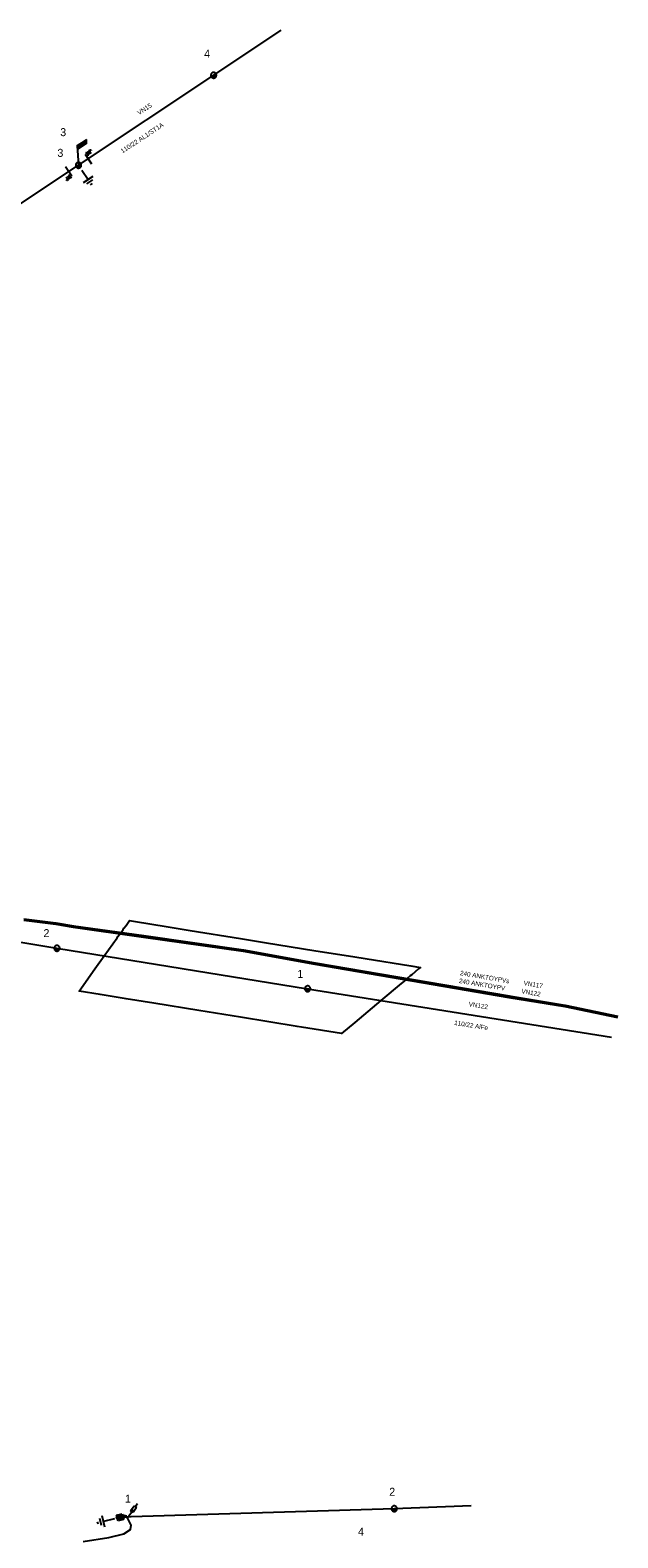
# Model space of a CAD drawing. Extents: x -540879 to -537255, y -1184046 to -1180016.
# Drawn here: x -537383.5 to -537255, y -1180686.9 to -1180357.2 of the extents above; entities that cross this region are included whole.
import ezdxf

# ---------------------------------------------------------------- set-up
doc = ezdxf.new("R2010")
doc.units = 0
for name, color, linetype in [('Default', 7, 'Continuous'), ('Vrstva 1', 7, 'Continuous'), ('Vrstva 11', 7, 'Continuous'), ('Vrstva 12', 7, 'Continuous'), ('Vrstva 13', 7, 'Continuous'), ('Vrstva 14', 7, 'Continuous'), ('Vrstva 15', 7, 'Continuous'), ('Vrstva 16', 7, 'Continuous'), ('Vrstva 18', 7, 'Continuous'), ('Vrstva 19', 7, 'Continuous'), ('Vrstva 2', 7, 'Continuous'), ('Vrstva 3', 7, 'Continuous'), ('Vrstva 35', 7, 'Continuous'), ('Vrstva 4', 7, 'Continuous'), ('Vrstva 5', 7, 'Continuous'), ('Vrstva 6', 7, 'Continuous'), ('Vrstva 7', 7, 'Continuous')]:
    doc.layers.add(name, color=color, linetype=linetype)

# ---------------------------------------------------------------- blocks, each defined once
blk = doc.blocks.new('VN840')
at = {"layer": 'Vrstva 15'}
for points in [[(-0.01, 1.41), (-0.01, -1.09)], [(-1.51, -1.24), (-1.51, -1.15)], [(-1.48, -1.35), (-1.51, -1.24)], [(-1.33, -1.42), (-1.48, -1.35)], [(-1.27, -1.42), (-1.33, -1.42)], [(-1.13, -1.35), (-1.27, -1.42)], [(-1.09, -1.24), (-1.13, -1.35)], [(-1.09, -0.59), (-1.09, -1.24)], [(-0.68, -0.59), (-0.68, -1.42)], [(-0.68, -1.11), (-0.27, -0.59)], [(-0.54, -0.94), (-0.2, -1.42)]]:
    blk.add_lwpolyline(points, dxfattribs=at)
blk = doc.blocks.new('VN440')
at = {"layer": 'Vrstva 2'}
for points in [[(1.22, 0), (1.21, 0.13), (1.19, 0.25), (1.16, 0.38), (1.11, 0.5), (1.05, 0.61), (0.98, 0.72), (0.9, 0.82), (0.81, 0.91), (0.71, 0.99), (0.6, 1.06), (0.49, 1.12), (0.37, 1.16), (0.25, 1.2), (0.12, 1.22), (-0.01, 1.22), (-0.14, 1.22), (-0.26, 1.2), (-0.39, 1.16), (-0.51, 1.12), (-0.62, 1.06), (-0.73, 0.99), (-0.83, 0.91), (-0.92, 0.82), (-1, 0.72), (-1.07, 0.61), (-1.13, 0.5), (-1.18, 0.38), (-1.21, 0.25), (-1.23, 0.13), (-1.24, 0), (-1.23, -0.13), (-1.21, -0.26), (-1.18, -0.38), (-1.13, -0.5), (-1.07, -0.62), (-1, -0.73), (-0.92, -0.83), (-0.83, -0.92), (-0.73, -1), (-0.62, -1.07), (-0.51, -1.13), (-0.39, -1.17), (-0.26, -1.2), (-0.14, -1.23), (-0.01, -1.23), (0.12, -1.23), (0.25, -1.2), (0.37, -1.17), (0.49, -1.13), (0.6, -1.07), (0.71, -1), (0.81, -0.92), (0.9, -0.83), (0.98, -0.73), (1.05, -0.62), (1.11, -0.5), (1.16, -0.38), (1.19, -0.26), (1.21, -0.13), (1.22, 0)], [(-1.24, 0), (1.22, 0)], [(-1.18, -0.34), (1.1, -0.34)], [(-1.01, -0.63), (0.97, -0.63)], [(-0.74, -0.92), (0.68, -0.92)]]:
    blk.add_lwpolyline(points, dxfattribs=at)
blk = doc.blocks.new('VN890')
at = {"layer": 'Vrstva 4'}
for points in [[(-0.41, 0.41), (0.41, 0)], [(-0.41, -0.41), (-0.41, 0.41)], [(0.41, 0), (-0.41, -0.41)], [(-0.34, 0.31), (0.27, 0), (-0.34, -0.3), (-0.34, 0.31)], [(-0.26, 0.2), (0.1, 0), (-0.26, -0.18), (-0.26, 0.2)], [(-0.19, 0.09), (-0.04, 0), (-0.19, -0.08), (-0.19, 0.09)], [(-0.16, -0.01), (-0.16, 0.03), (-0.13, 0.01), (-0.16, -0.01)]]:
    blk.add_lwpolyline(points, dxfattribs=at)
blk = doc.blocks.new('VN820')
at = {"layer": 'Vrstva 13'}
for points in [[(0, 0), (0, -2.1)], [(-0.32, -1.63), (0.34, -1.63)], [(-0.32, -2.95), (-0.32, -1.63)], [(0.34, -2.95), (-0.32, -2.95)], [(0, -2.1), (-0.12, -1.86)], [(0, -2.1), (0.12, -1.86)], [(0, -2.95), (0, -3.75)], [(0.34, -1.63), (0.34, -2.95)]]:
    blk.add_lwpolyline(points, dxfattribs=at)
blk = doc.blocks.new('VN810')
at = {"layer": 'Vrstva 14'}
for points in [[(0, -1.25), (0, -3.75)], [(1.25, -3.75), (-1.25, -3.75)], [(0.77, -4.37), (-0.8, -4.37)], [(0, -5), (-0.25, -5)], [(0.27, -5), (0, -5)]]:
    blk.add_lwpolyline(points, dxfattribs=at)
blk = doc.blocks.new('VN001')
at = {"layer": 'Default'}
for p, q in [((1.9, 3.33), (4.32, 3.33)), ((1.93, 3.38), (4.35, 3.38)), ((1.96, 3.43), (4.37, 3.43)), ((1.99, 3.48), (4.4, 3.48)), ((2.02, 3.53), (4.43, 3.53)), ((2.05, 3.58), (4.46, 3.58)), ((2.07, 3.63), (4.49, 3.63)), ((2.1, 3.68), (4.52, 3.68)), ((2.13, 3.73), (2.54, 3.73)), ((1.73, 3.03), (4.14, 3.03)), ((1.76, 3.08), (4.17, 3.08)), ((1.79, 3.13), (4.2, 3.13)), ((1.82, 3.18), (4.23, 3.18)), ((1.85, 3.23), (4.26, 3.23)), ((1.87, 3.28), (4.29, 3.28))]:
    blk.add_line(p, q, dxfattribs=at)
blk.add_lwpolyline([(2.13, 3.73), (0, 0)], dxfattribs=at)
blk.add_lwpolyline([(4.55, 3.73), (2.13, 3.73), (1.7, 2.98), (4.12, 2.99)], close=True, dxfattribs=at)
blk = doc.blocks.new('VN470')
at = {"layer": 'Vrstva 2'}
for points in [[(-1.23, 1.22), (1.23, 1.22)], [(-1.23, -1.23), (-1.23, 1.22)], [(-0.92, 0.9), (0.92, 0.9)], [(-0.92, -0.95), (-0.92, 0.9)], [(-0.61, 0.61), (0.61, 0.61)], [(-0.61, -0.62), (-0.61, 0.61)], [(-0.31, -0.27), (-0.31, 0.34)], [(-0.31, 0.34), (0.31, 0.34)], [(0, 1.22), (0, 1.97)], [(0.31, 0.34), (0.31, -0.27)], [(0.61, 0.61), (0.61, -0.62)], [(0.92, 0.9), (0.92, -0.95)], [(1.23, 1.22), (1.23, -1.23)], [(1.23, -1.23), (-1.23, -1.23)], [(0.92, -0.95), (-0.92, -0.95)], [(0.61, -0.62), (-0.61, -0.62)], [(0.31, -0.27), (-0.31, -0.27)], [(0, -1.23), (0, -1.98)]]:
    blk.add_lwpolyline(points, dxfattribs=at)

msp = doc.modelspace()

# ---------------------------------------------------------------- linework, layer by layer
at = {"layer": 'Vrstva 1'}
for points in [[(-537372.88, -1180386.77), (-537343.33, -1180367.08), (-537328.56, -1180357.22)], [(-537402.58, -1180406.43), (-537372.88, -1180386.77)], [(-537402.28, -1180553.89), (-537377.59, -1180557.99), (-537322.79, -1180566.84), (-537256.34, -1180577.46)], [(-537287.02, -1180679.9), (-537303.84, -1180680.55), (-537363.8, -1180682.43)]]:
    msp.add_lwpolyline(points, dxfattribs=at)
at = {"layer": 'Vrstva 35'}
msp.add_lwpolyline([(-537360.89, -1180552.08), (-537353.3, -1180553.3), (-537348.46, -1180554.08), (-537337.5, -1180555.86), (-537331.78, -1180556.78), (-537321.44, -1180558.45), (-537312.5, -1180559.88), (-537310.24, -1180560.24), (-537300.26, -1180561.83), (-537298.13, -1180562.17), (-537298.52, -1180562.5), (-537300.04, -1180563.78), (-537300.35, -1180564.03), (-537301.05, -1180564.62), (-537301.35, -1180564.87), (-537302.05, -1180565.46), (-537302.36, -1180565.72), (-537306.75, -1180569.4), (-537312.5, -1180574.22), (-537315.38, -1180576.63), (-537324.14, -1180575.23), (-537325.08, -1180575.08), (-537337.5, -1180573.07), (-537346.6, -1180571.6), (-537356.39, -1180570.02), (-537362.5, -1180569.04), (-537368.13, -1180568.13), (-537372.76, -1180567.38), (-537369.28, -1180562.5), (-537367.25, -1180559.66), (-537364.44, -1180555.72), (-537364.25, -1180555.45), (-537363.79, -1180554.8), (-537363.59, -1180554.53), (-537363.13, -1180553.89), (-537362.94, -1180553.61), (-537362.5, -1180552.99), (-537361.74, -1180551.94)], close=True, dxfattribs=at)
at = {"layer": 'Vrstva 5'}
for points in [[(-537384.86, -1180551.85), (-537377.85, -1180552.73), (-537374.02, -1180553.35), (-537358.66, -1180555.53), (-537336.87, -1180558.61), (-537321.18, -1180561.49), (-537278.79, -1180568.73), (-537266.53, -1180570.72), (-537255.05, -1180573.15)], [(-537384.82, -1180551.55), (-537377.81, -1180552.43), (-537373.97, -1180553.06), (-537358.61, -1180555.23), (-537336.82, -1180558.32), (-537321.12, -1180561.19), (-537278.74, -1180568.43), (-537266.47, -1180570.43), (-537254.97, -1180572.86)], [(-537371.83, -1180687.72), (-537366.25, -1180686.86), (-537363.01, -1180686.02), (-537361.48, -1180685.1), (-537361.36, -1180684.18), (-537362.15, -1180682.51), (-537363.12, -1180682.26), (-537363.8, -1180682.43)]]:
    msp.add_lwpolyline(points, dxfattribs=at)

# ---------------------------------------------------------------- block references
at = {"layer": 'Vrstva 11', "rotation": 33.72583887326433}
msp.add_blockref('VN001', (-537372.88, -1180386.77), dxfattribs=at)
at = {"layer": 'Vrstva 13'}
for name, p, xscale, yscale, rotation in [('VN440', (-537343.33, -1180367.08), 0.5, 0.5, 33.71625696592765), ('VN440', (-537372.88, -1180386.77), 0.5, 0.49999999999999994, 33.681768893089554), ('VN440', (-537377.59, -1180557.99), 0.49999999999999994, 0.5, -9.494450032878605), ('VN440', (-537322.79, -1180566.84), 0.5, 0.5000000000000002, -9.05749734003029), ('VN440', (-537303.84, -1180680.55), 0.5, 0.5, 1.7932083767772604), ('VN470', (-537363.8, -1180682.43), 0.5, 0.5000000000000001, 104.27390276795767)]:
    msp.add_blockref(name, p, dxfattribs=dict(at, xscale=xscale, yscale=yscale, rotation=rotation))
at = {"layer": 'Vrstva 15'}
for p, rotation in [((-537372.88, -1180386.77), 33.726074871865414), ((-537363.8, -1180682.43), -75.9637555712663)]:
    msp.add_blockref('VN810', p, dxfattribs=dict(at, rotation=rotation))
at = {"layer": 'Vrstva 16', "rotation": 145.1834055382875}
msp.add_blockref('VN820', (-537362.15, -1180682.51), dxfattribs=at)
at = {"layer": 'Vrstva 18'}
for p, rotation in [((-537370.73, -1180385.34), -146.60114536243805), ((-537374.97, -1180388.17), 33.725644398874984)]:
    msp.add_blockref('VN840', p, dxfattribs=dict(at, rotation=rotation))
at = {"layer": 'Vrstva 19', "rotation": 14.258491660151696}
msp.add_blockref('VN890', (-537362.77, -1180682.21), dxfattribs=at)

# ---------------------------------------------------------------- texts
at = {"layer": 'Vrstva 12'}
msp.add_text('3', height=1.75, dxfattribs=at).set_placement((-537376.88, -1180380.4))
at = {"layer": 'Vrstva 14'}
for s, p in [('4', (-537345.41, -1180363.24)), ('3', (-537377.5, -1180384.93)), ('2', (-537380.55, -1180555.56)), ('1', (-537325.03, -1180564.47)), ('1', (-537362.72, -1180679.23)), ('2', (-537304.95, -1180677.73)), ('4', (-537311.76, -1180686.42))]:
    msp.add_text(s, height=1.75, dxfattribs=at).set_placement(p)
at = {"layer": 'Vrstva 2'}
for s, rotation, p in [('110/22 AL1/ST1A', 33.395, (-537363.26, -1180384.2)), ('110/22 AlFe', 350.919, (-537290.8, -1180574.74))]:
    msp.add_text(s, height=1, rotation=rotation, dxfattribs=at).set_placement(p)
at = {"layer": 'Vrstva 3'}
for s, rotation, p in [('VN15', 33.395, (-537359.61, -1180375.84)), ('VN122', 350.919, (-537287.63, -1180570.67))]:
    msp.add_text(s, height=1, rotation=rotation, dxfattribs=at).set_placement(p)
at = {"layer": 'Vrstva 6'}
for s, rotation, p in [('240 ANKTOYPV', 350.312, (-537289.76, -1180565.56)), ('240 ANKTOYPVs', 350.313, (-537289.52, -1180563.85))]:
    msp.add_text(s, height=1, rotation=rotation, dxfattribs=at).set_placement(p)
at = {"layer": 'Vrstva 7'}
for s, rotation, p in [('VN117', 350.313, (-537275.62, -1180566.05)), ('VN122', 350.312, (-537276.1, -1180567.84))]:
    msp.add_text(s, height=1, rotation=rotation, dxfattribs=at).set_placement(p)

doc.saveas('drawing.dxf')
